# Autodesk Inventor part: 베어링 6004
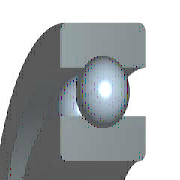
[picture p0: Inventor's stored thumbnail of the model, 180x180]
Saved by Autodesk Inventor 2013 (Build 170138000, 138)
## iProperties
IsCustomPart: 1
Created: 2012-02
Part Number: 베어링 6004
Material: 강철, 연강
Description: 깊은 그루브 볼 베어링
Document SubType Name: Modeling
Standard: KS B 2023
Designer: mduedu
Standards Organization: KS
Language: ko-KR
Size Designation: 6004 - 20 x 42 x 12
Categories: <MemberInstance><Categories><Category DisplayName="샤프트 부품" InternalName="7f7aeb1f-a693-4053-b835-cee3144e0d98" Mnemonic="SHFT"><Category DisplayName="베어링" Inter
Density: 7.86 g/cm^3
Mass: 68.3136 g
Surface Area: 70.0178 cm^2
Volume: 8.6913 cm^3
Author: mduedu
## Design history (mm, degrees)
sketch "스케치" dims "d0" = 5.72 (= -0.26 x WD + 0.26 x BD)
  geometry: L1 (3.14, 15.5)-(8.86, 15.5); L2 (6, 15.5)-(6, 12.64); L3 (6, 15.5)-(6, 18.36); L4 (3.875, 13.586)-(0, 13.586); L5 (0, 10)-(12, 10); L6 (3.875, 17.414)-(0, 17.414); L7 (0, 21)-(12, 21); L8 (12, 10)-(12, 13.586); L9 (8.125, 13.586)-(12, 13.586); L10 (8.125, 17.414)-(12, 17.414); L11 (12, 21)-(12, 17.414); L12 (-1.4, 0)-(8.4, 0) reference; L13 (0, -0.3)-(0, 5.3) reference
  constraints: 22 end point, 4 point on line, 2 collinear, 2 perpendicular, 2 symmetric about line, 1 midpoint, 1 parallel, 14 other
  dimensions: "d9" = 20 diameter of L5 L12 (= WD); "d11" = 42 diameter of L7 L12 (= BD); "d12" = 12 distance between parallel lines of L8 L13 (= KB); "d13" = 27.172 diameter of L9 L12 (= 0.326 x BD + 0.674 x WD)
revolve "본체" stored, may be unused: angle "d6" = 90 deg
revolve "볼" stored, may be unused: angle "d7" = 90 deg
pattern_circular "IDS_ARRAYBALL[SIMPL:T]" dims angle "d3" = 360 deg
body "Solid1"
fillet "모깎기1" dims "d1" = 0.6 (= KRS)
other parameters: "WD" = 20 [user parameter; used in 5 equation terms], "BD" = 42 [user parameter; used in 5 equation terms], "KB" = 12 [user parameter; used in 1 equation term], "KRS" = 0.6 [user parameter; used in 1 equation term], "d4" = 0, "d5" = 0, "d8" = 0, "d14" = 0, "d15" = 0, "BBA" = 0 [user parameter], "BC0" = 5000000 [user parameter], "BC" = 9360000 [user parameter], "BR" = 21 (= 0.5 x BD) [user parameter]
